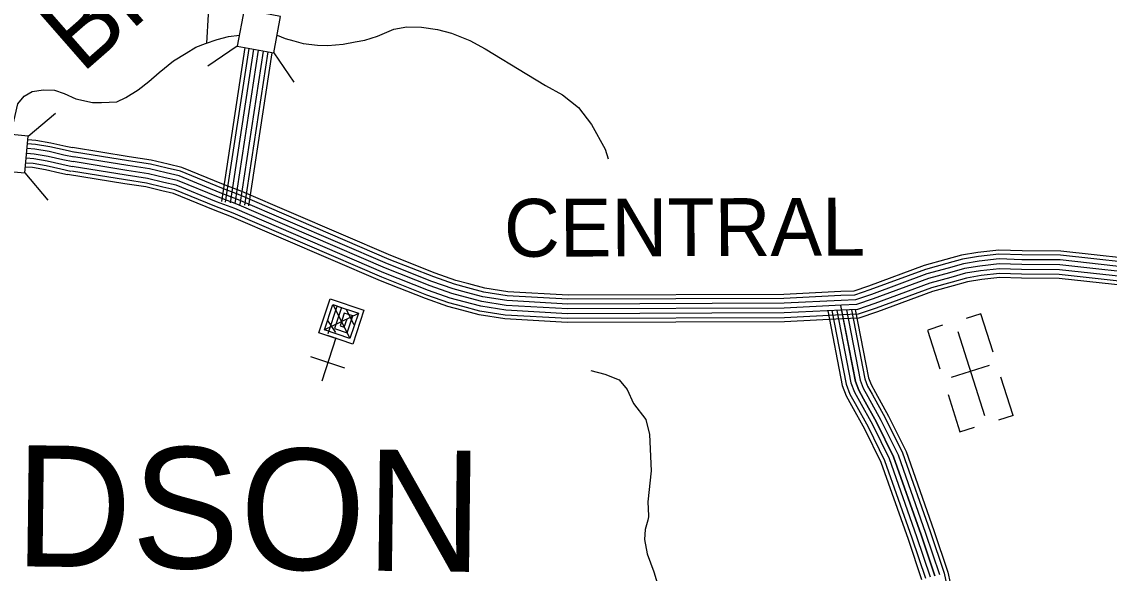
# Model space of a CAD drawing. Extents: x 1788175 to 1969470, y 584502 to 738744.
# Drawn here: x 1820550 to 1827505, y 658898 to 662427 of the extents above; entities that cross this region are included whole.
import ezdxf

# ---------------------------------------------------------------- set-up
doc = ezdxf.new("R2010")
doc.units = 0
for name, color, linetype in [('DESIGN - DRAINAGE - Bridges and Cross Drains Size Text', 7, 'Continuous'), ('DESIGN - ROW - Right-of-Way and Easement Labels', 7, 'Continuous'), ('DESIGN - TRANSPORTATION - Text', 7, 'Continuous'), ('DESIGN - UTILITIES - Cable (Underground) with Text', 7, 'Continuous'), ('SURVEY - CONTROL with Text', 7, 'Continuous'), ('SURVEY - DRAINAGE - Natural Features', 7, 'Continuous'), ('SURVEY - DRAINAGE - Storm Sewer', 7, 'Continuous'), ('SURVEY - TRANSPORTATION - Roads', 7, 'Continuous')]:
    doc.layers.add(name, color=color, linetype=linetype)

msp = doc.modelspace()

# ---------------------------------------------------------------- linework, layer by layer
at = {"layer": 'DESIGN - TRANSPORTATION - Text'}
for points in [[(1822588.9, 663513), (1822529.7, 663376.5), (1822488.6, 663331.3), (1822431.1, 663298.5), (1822390, 663277.9), (1822357.1, 663265.6), (1822316.1, 663261.5), (1822246.2, 663257.4), (1822225.7, 663253.3), (1822188.7, 663249.2), (1822114.8, 663241), (1822036.7, 663220.4), (1822007.9, 663208.1), (1821962.8, 663179.4), (1821942.2, 663167), (1821913.5, 663134.2), (1821892.9, 663101.3), (1821851.8, 663043.8), (1821831.3, 662998.6), (1821802.5, 662891.8), (1821786.1, 662821.9), (1821753.2, 662674.1), (1821740.9, 662472.8), (1821731.9, 662290.4)], [(1822183, 662340.7), (1822234.4, 662318.7), (1822290.2, 662304), (1822349.9, 662287.2), (1822441.7, 662276.1), (1822507.6, 662275.3), (1822605.6, 662284.1), (1822681.7, 662299.2), (1822743.8, 662308.5), (1822824, 662335.5), (1822928.4, 662378.3), (1823012.5, 662393.3), (1823106.4, 662392.1), (1823208.1, 662376.8), (1823297.8, 662353.7), (1823415.1, 662306.2), (1823514.3, 662253), (1823780.1, 662091.6), (1823899.1, 662018.1), (1824008.3, 661958.7), (1824111.2, 661877.3), (1824193.8, 661770.2), (1824279.8, 661611), (1824299.6, 661550.5)], [(1820480.5, 661705.8), (1820524.9, 661901.7), (1820566, 661951), (1820615.3, 661979.8), (1820689.2, 661992.1), (1820759.1, 661988), (1820820.7, 661967.5), (1820894.6, 661934.6), (1821001.5, 661909.9), (1821059, 661909.9), (1821157.6, 661914), (1821215.1, 661942.8), (1821293.1, 661992.1), (1821363, 662045.5), (1821428.7, 662103), (1821519.1, 662177), (1821601.2, 662226.3), (1821662.9, 662263.2), (1821724.5, 662287.9), (1821798.4, 662312.5), (1821872.4, 662333.1), (1821941.4, 662341.7)], [(1824188.5, 660195.7), (1824278, 660172.1), (1824369.3, 660136.4), (1824422.1, 660073.4), (1824462.5, 659984.6), (1824540.5, 659881.1), (1824564.8, 659786.6), (1824574.7, 659554.1), (1824553.2, 659354.3), (1824557.6, 659266.1), (1824558.1, 659258.3)], [(1824558.1, 659258.3), (1824554, 659236.9), (1824537, 659179.1), (1824531.9, 659113.2), (1824550.2, 659022.7), (1824592.1, 658907.9), (1824622.4, 658809.2)]]:
    msp.add_lwpolyline(points, dxfattribs=at)
at = {"layer": 'DESIGN - UTILITIES - Cable (Underground) with Text'}
for p, q in [((1826683.5, 660558.5), (1826588.4, 660528.2)), ((1826761.2, 660313.7), (1826683.4, 660558.4)), ((1826342.7, 660454.3), (1826421.7, 660205.7)), ((1826437.7, 660484.5), (1826343.3, 660454.4)), ((1822397.2, 660284.8), (1822613.7, 660212.9)), ((1826736.1, 660227.7), (1826494.4, 660150.8)), ((1826890.4, 659907.3), (1826812.2, 660153.3)), ((1826473.5, 660042.8), (1826549.7, 659803.2)), ((1826890.2, 659907.3), (1826795.4, 659877.1)), ((1826549.8, 659803.2), (1826643.4, 659832.9))]:
    msp.add_line(p, q, dxfattribs=at)
for points in [[(1822556.5, 660395.9), (1822558.1, 660400.7), (1822449.9, 660436.7), (1822521.8, 660653.2), (1822738.3, 660581.2), (1822666.3, 660364.8), (1822504, 660418.7), (1822505.2, 660422.6)], [(1822508.5, 660432.2), (1822566.9, 660608.1), (1822702.2, 660563.1), (1822648.2, 660400.8), (1822485.9, 660454.8), (1822539.9, 660617.1), (1822594, 660599.1), (1822549, 660463.8), (1822630.2, 660436.8), (1822666.2, 660545.1), (1822612.1, 660563.1), (1822585, 660481.9), (1822612.1, 660472.9), (1822630.1, 660527)], [(1822648.4, 660403.7), (1822540.3, 660614.8)], [(1822676, 660486.8), (1822623.3, 660587.2)], [(1822484.2, 660455.3), (1822704.5, 660563.3)], [(1822558.9, 660439.6), (1822507.2, 660515.3)], [(1826535.5, 660444.9), (1826706.1, 659908.3)], [(1822470.6, 660129.9), (1822559.9, 660406.3)]]:
    msp.add_lwpolyline(points, dxfattribs=at)
at = {"layer": 'SURVEY - CONTROL with Text'}
for points in [[(1820587.3, 661648.2), (1820637.4, 661644.2), (1820730.2, 661628.6), (1820826.5, 661606.4), (1820890.6, 661592.5)], [(1820589.5, 661672.8), (1820640.5, 661668.7), (1820735.1, 661652.8), (1820831.9, 661630.5), (1820874.2, 661621.4)], [(1827815.7, 660890.2), (1827193.8, 660959.2), (1826946.6, 660961.3), (1826797.5, 660965.8), (1826664.8, 660950.9), (1826559.9, 660933.4), (1826459, 660905.7), (1826320.9, 660866.9), (1825964.8, 660735.8), (1825871.2, 660703.9), (1825787.5, 660700.1), (1825423.4, 660682.3), (1824043.4, 660677.4), (1823657.2, 660699.5), (1823510.4, 660722.8), (1823409.4, 660749.4), (1823325.4, 660771.9), (1823193, 660818.6), (1822909.9, 660930.4), (1821957, 661341), (1821839.2, 661385.3), (1821572.9, 661494.8), (1821486.1, 661514.5), (1821377.2, 661540.8), (1821236.2, 661562.2), (1820874.2, 661621.4)], [(1820578.8, 661555.6), (1820626, 661551.8), (1820712.1, 661537.3), (1820806.2, 661515.6), (1820871, 661501.6)], [(1820581.7, 661586.5), (1820629.8, 661582.6), (1820718.1, 661567.7), (1820813, 661545.9), (1820877.5, 661531.9)], [(1820584.5, 661617.4), (1820633.6, 661613.4), (1820724.2, 661598.2), (1820819.7, 661576.1), (1820884.1, 661562.2)], [(1827808.7, 660833.9), (1827190.4, 660902.5), (1826945.5, 660904.5), (1826799.8, 660909), (1826672.7, 660894.7), (1826572.1, 660877.9), (1826474.2, 660851.1), (1826338.4, 660812.9), (1825983.8, 660682.4), (1825881.8, 660647.7), (1825790.2, 660643.5), (1825424.9, 660625.6), (1824041.8, 660620.6), (1823651.1, 660643.1), (1823498.7, 660667.2), (1823394.9, 660694.6), (1823308.6, 660717.7), (1823173.2, 660765.5), (1822888.3, 660878), (1821935.8, 661288.4), (1821818.4, 661332.5), (1821555.8, 661440.5), (1821473.2, 661459.3), (1821366.3, 661485.1), (1821227.3, 661506.2), (1820882.5, 661562.5)], [(1827812.6, 660864.7), (1827192.3, 660933.5), (1826946.1, 660935.5), (1826798.6, 660940.1), (1826668.4, 660925.4), (1826565.5, 660908.3), (1826465.9, 660880.9), (1826328.8, 660842.4), (1825973.4, 660711.6), (1825876, 660678.4), (1825788.7, 660674.4), (1825424.1, 660656.6), (1824042.7, 660651.6), (1823654.4, 660673.9), (1823505.1, 660697.6), (1823402.8, 660724.5), (1823317.7, 660747.4), (1823184, 660794.5), (1822900.1, 660906.6), (1821947.4, 661317.1), (1821829.8, 661361.3), (1821565.1, 661470.2), (1821480.2, 661489.5), (1821372.2, 661515.5), (1821232.2, 661536.8), (1820887.5, 661593.1)], [(1820573.7, 661499.1), (1820618.9, 661495.5), (1820701, 661481.7), (1820793.9, 661460.2), (1820841.7, 661449.9)], [(1820576, 661524.7), (1820622.1, 661521), (1820706, 661506.9), (1820799.5, 661485.3), (1820864.5, 661471.3)], [(1827801, 660772.4), (1827186.8, 660840.5), (1826944.3, 660842.5), (1826802.4, 660846.9), (1826681.3, 660833.3), (1826585.5, 660817.3), (1826490.7, 660791.3), (1826357.5, 660753.9), (1826004.5, 660623.9), (1825893.5, 660586.1), (1825793.1, 660581.5), (1825426.5, 660563.6), (1824040.2, 660558.6), (1823644.4, 660581.4), (1823485.9, 660606.5), (1823378.9, 660634.7), (1823290.2, 660658.5), (1823151.5, 660707.4), (1822864.6, 660820.7), (1821912.6, 661230.9), (1821795.7, 661274.8), (1821537, 661381.2), (1821459, 661398.9), (1821354.3, 661424.2), (1821217.7, 661444.9), (1820872.5, 661501.3)], [(1827804.9, 660803.1), (1827188.6, 660871.5), (1826944.9, 660873.5), (1826801.1, 660877.9), (1826677, 660864), (1826578.8, 660847.6), (1826482.5, 660821.2), (1826348, 660783.4), (1825994.1, 660653.2), (1825887.6, 660616.9), (1825791.7, 660612.5), (1825425.7, 660594.6), (1824041, 660589.6), (1823647.8, 660612.2), (1823492.3, 660636.8), (1823386.9, 660664.6), (1823299.4, 660688.1), (1823162.3, 660736.4), (1822876.5, 660849.3), (1821924.2, 661259.6), (1821807.1, 661303.6), (1821546.4, 661410.9), (1821466.1, 661429.1), (1821360.3, 661454.6), (1821222.5, 661475.5), (1820877.5, 661531.9)], [(1827794.1, 660717.1), (1827183.4, 660784.8), (1826943.2, 660786.8), (1826804.6, 660791.1), (1826689, 660778.1), (1826597.4, 660762.8), (1826505.7, 660737.6), (1826374.7, 660700.8), (1826023.1, 660571.4), (1825903.9, 660530.8), (1825795.8, 660525.9), (1825428, 660507.9), (1824038.7, 660502.9), (1823638.5, 660525.9), (1823474.5, 660551.9), (1823364.6, 660580.8), (1823273.7, 660605.2), (1823132, 660655.2), (1822843.4, 660769.2), (1821891.8, 661179.2), (1821775.3, 661222.9), (1821520.1, 661327.9), (1821446.3, 661344.7), (1821343.6, 661369.5), (1821209, 661389.9), (1820841.7, 661449.9)], [(1827797.2, 660741.6), (1827184.9, 660809.5), (1826943.7, 660811.6), (1826803.6, 660815.8), (1826685.5, 660802.6), (1826592.1, 660787), (1826499, 660761.5), (1826367.1, 660724.4), (1826014.8, 660594.7), (1825899.3, 660555.4), (1825794.6, 660550.6), (1825427.3, 660532.6), (1824039.3, 660527.6), (1823641.1, 660550.5), (1823479.5, 660576.1), (1823371, 660604.7), (1823281, 660628.8), (1823140.6, 660678.3), (1822852.8, 660792), (1821901, 661202.1), (1821784.4, 661245.9), (1821527.6, 661351.5), (1821451.9, 661368.7), (1821348.3, 661393.7), (1821212.9, 661414.3), (1820867.5, 661470.7)]]:
    msp.add_lwpolyline(points, dxfattribs=at)
at = {"layer": 'SURVEY - DRAINAGE - Storm Sewer'}
for p, q in [((1821928.1, 662270.6), (1821740.6, 662142.3)), ((1822161.6, 662226.8), (1822289.9, 662039.3)), ((1820591.6, 661695.7), (1820766.1, 661841.1)), ((1820570, 661459.1), (1820715.4, 661284.6))]:
    msp.add_line(p, q, dxfattribs=at)
for points in [[(1822161.6, 662226.8), (1822205.4, 662460.3), (1821971.9, 662504.1), (1821928.1, 662270.6)], [(1820333.5, 661480.6), (1820570.1, 661459.1), (1820591.6, 661695.7), (1820355, 661717.2)]]:
    msp.add_lwpolyline(points, close=True, dxfattribs=at)
at = {"layer": 'SURVEY - TRANSPORTATION - Roads'}
for points in [[(1821829.1, 661276.2), (1821979.2, 662261)], [(1821853.5, 661272.5), (1822003.6, 662256.4)], [(1821884.1, 661267.8), (1822034, 662250.7)], [(1821914.8, 661263.2), (1822064.5, 662245)], [(1821914.8, 661263.2), (1822064.5, 662245)], [(1821945.4, 661258.5), (1822095, 662239.3)], [(1821976.1, 661253.8), (1822125.5, 662233.5)], [(1822001.5, 661249.9), (1822150.8, 662228.8)], [(1825704.6, 660577.2), (1825796.8, 660100.1), (1825822.8, 660033), (1825856.8, 659971), (1825939.3, 659823.2), (1826044.2, 659609.9), (1826217.8, 659116), (1826303.6, 658859.3)], [(1825730.5, 660578.5), (1825821.6, 660107.3), (1825846.2, 660043.8), (1825879.3, 659983.5), (1825962.1, 659835.1), (1826068, 659619.8), (1826242.1, 659124.3), (1826328.5, 658866.2)], [(1825761.8, 660580), (1825851.5, 660115.9), (1825874.4, 660057), (1825906.4, 659998.5), (1825989.5, 659849.5), (1826096.6, 659631.9), (1826271.4, 659134.4), (1826358.4, 658874.4)], [(1826388.3, 658882.7), (1826300.8, 659144.4), (1826125.2, 659643.9), (1826017, 659863.9), (1825933.6, 660013.5), (1825902.5, 660070.1), (1825881.5, 660124.5), (1825787.2, 660612.3)], [(1825793.1, 660581.5), (1825881.5, 660124.5), (1825902.5, 660070.1), (1825933.6, 660013.5), (1826017, 659863.9), (1826125.2, 659643.9), (1826300.8, 659144.4), (1826388.3, 658882.7)], [(1825824.4, 660583), (1825911.4, 660133.1), (1825930.7, 660083.2), (1825960.7, 660028.5), (1826044.5, 659878.3), (1826153.9, 659655.9), (1826330.1, 659154.5), (1826418.2, 658891)], [(1825855.7, 660584.4), (1825941.3, 660141.7), (1825958.9, 660096.3), (1825987.8, 660043.5), (1826071.9, 659892.7), (1826182.5, 659667.9), (1826359.4, 659164.6), (1826448.2, 658899.2), (1826477.5, 658765.7)], [(1825880.6, 660585.5), (1825965.1, 660148.6), (1825981.3, 660106.7), (1826009.4, 660055.5), (1826093.8, 659904.2), (1826205.3, 659677.5), (1826382.8, 659172.6), (1826472, 658905.8), (1826502, 658769.5)]]:
    msp.add_lwpolyline(points, dxfattribs=at)

# ---------------------------------------------------------------- texts
at = {"layer": 'DESIGN - DRAINAGE - Bridges and Cross Drains Size Text'}
msp.add_text('Br.', height=475, rotation=41.18953, dxfattribs=at).set_placement((1820933.5, 662090.9))
at = {"layer": 'DESIGN - ROW - Right-of-Way and Easement Labels'}
msp.add_text('CENTRAL', height=370, rotation=0.20378, dxfattribs=at).set_placement((1823634, 660922.8))
at = {"layer": 'SURVEY - DRAINAGE - Natural Features'}
msp.add_text('DAVIDSON', height=775, rotation=359.29041, dxfattribs=at).set_placement((1818081.7, 658973.1))

doc.saveas('drawing.dxf')
